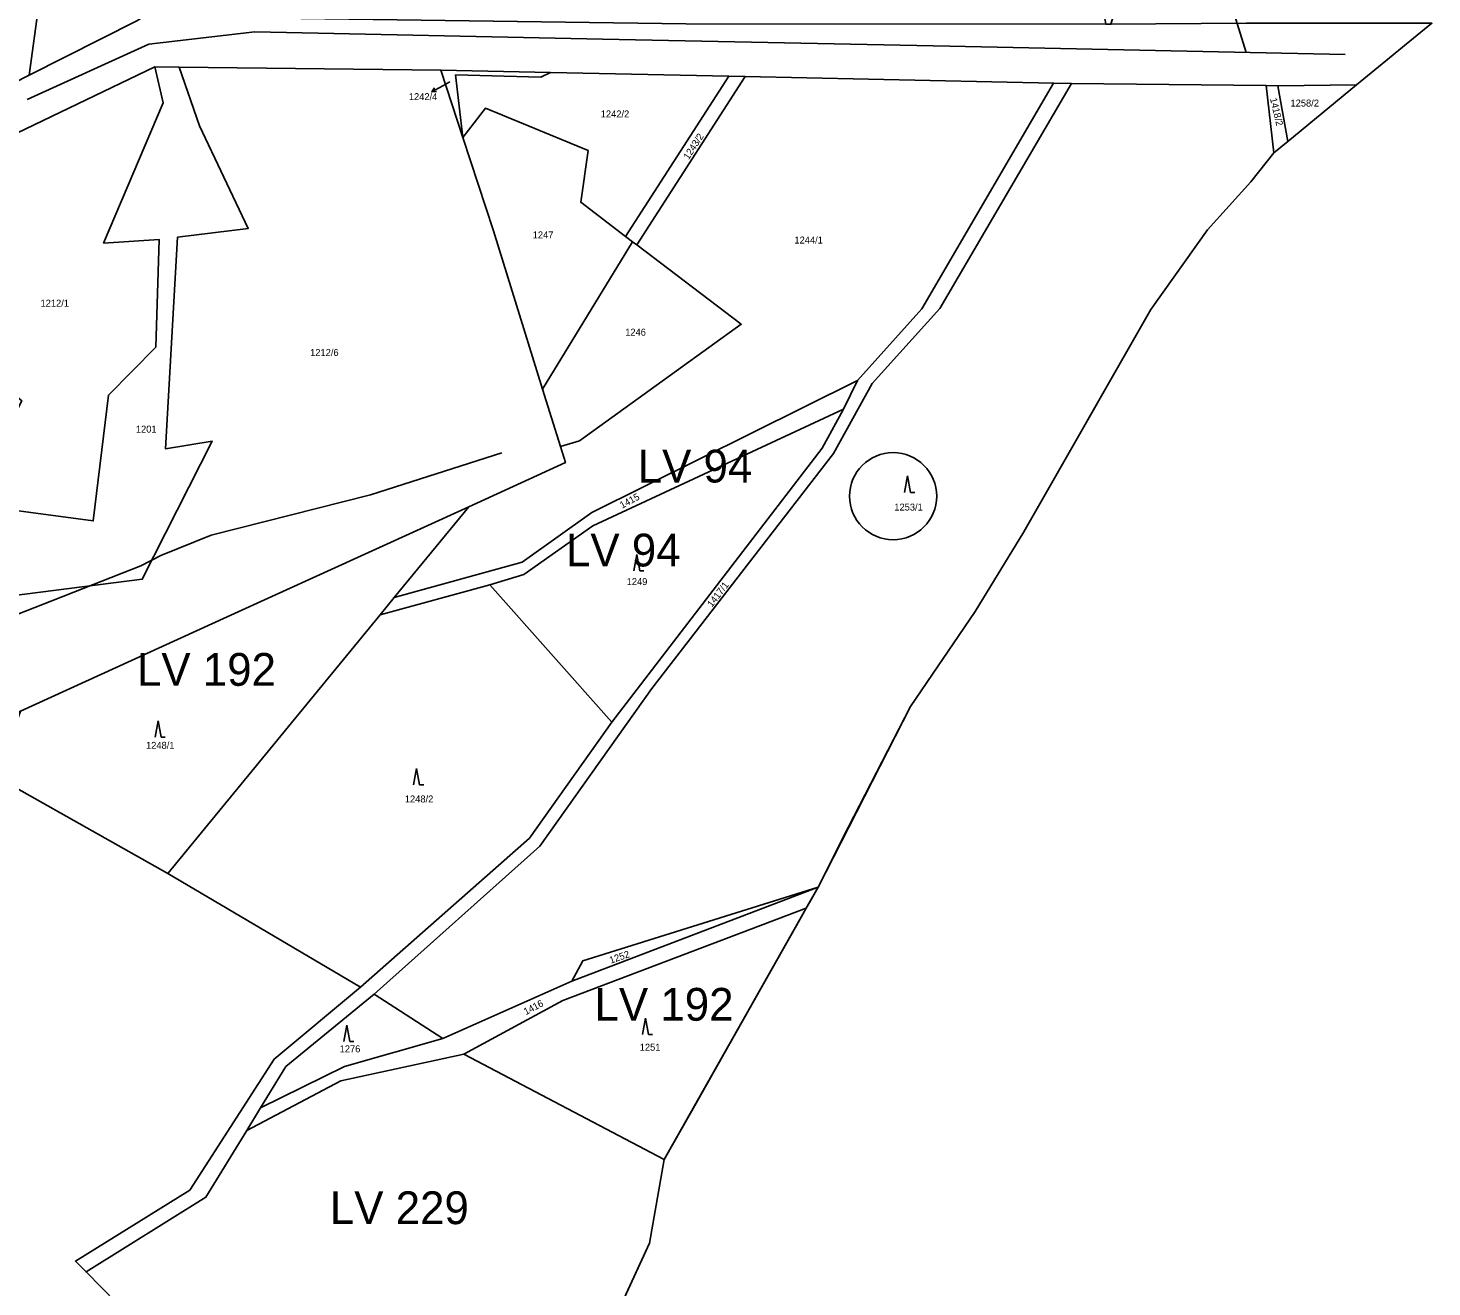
# Model space of a CAD drawing. Extents: x -588699 to -585793, y -1060280 to -1056731.
# Drawn here: x -587141.3 to -586798.8, y -1059816.3 to -1059509.1 of the extents above; entities that cross this region are included whole.
import ezdxf

# ---------------------------------------------------------------- set-up
doc = ezdxf.new("R2010")
doc.units = 0
for name, color, linetype in [('Druh pozemku', 7, 'Continuous'), ('Lesy', 7, 'Continuous'), ('Parcela nároku', 7, 'Continuous'), ('Parcelní číslo', 7, 'Continuous'), ('Silnice', 7, 'Continuous'), ('Vnitřní obvod', 7, 'Continuous'), ('Vnější obvod', 7, 'Continuous'), ('Vnější obvod_k šeření', 7, 'Continuous'), ('Vnější obvod_převzatý', 7, 'Continuous'), ('Změna katastrální hranice', 7, 'Continuous')]:
    doc.layers.add(name, color=color, linetype=linetype)

msp = doc.modelspace()

# ---------------------------------------------------------------- linework, layer by layer
at = {"layer": 'Druh pozemku'}
for p, q in [((-586926.71, -1059618.38), (-586927.45, -1059622.38)), ((-586926.71, -1059618.38), (-586925.98, -1059622.38)), ((-586925.98, -1059622.38), (-586924.98, -1059622.38)), ((-586992.76, -1059637.58), (-586993.49, -1059641.58)), ((-586992.76, -1059637.58), (-586992.03, -1059641.58)), ((-586992.03, -1059641.58), (-586991.03, -1059641.58)), ((-587109.57, -1059678.13), (-587110.31, -1059682.13)), ((-587109.57, -1059678.13), (-587108.84, -1059682.13)), ((-587108.84, -1059682.13), (-587107.84, -1059682.13)), ((-587046.49, -1059689.78), (-587047.22, -1059693.78)), ((-587046.49, -1059689.78), (-587045.76, -1059693.78)), ((-587045.76, -1059693.78), (-587044.76, -1059693.78)), ((-587063.55, -1059752.41), (-587064.29, -1059756.41)), ((-587063.55, -1059752.41), (-587062.82, -1059756.41)), ((-586990.66, -1059750.71), (-586991.4, -1059754.71)), ((-586990.66, -1059750.71), (-586989.93, -1059754.71)), ((-587062.82, -1059756.41), (-587061.82, -1059756.41)), ((-586989.93, -1059754.71), (-586988.93, -1059754.71))]:
    msp.add_line(p, q, dxfattribs=at)
at = {"layer": 'Lesy'}
msp.add_lwpolyline([(-587141.05, -1059520.54), (-587119.83, -1059365.24), (-587078.9, -1059331.95), (-586969.62, -1059361.59), (-586966.76, -1059361.84), (-586956.3, -1059359.21), (-586947.21, -1059358.99), (-586942.18, -1059361.29), (-586936.22, -1059370.55), (-586923.3, -1059391.32), (-586910.39, -1059412.1), (-586900.48, -1059424.78), (-586873.49, -1059457.5), (-586863.97, -1059469.8), (-586867.63, -1059482.1), (-586871.32, -1059488.5), (-586875.06, -1059501.23), (-586877.11, -1059508.12), (-586878.33, -1059508.13), (-586980.84, -1059508.07), (-587033.64, -1059507.3), (-587086.44, -1059506.54), (-587099.64, -1059497.72), (-587114.74, -1059507.28)], close=True, dxfattribs=at)
at = {"layer": 'Parcela nároku'}
for points in [[(-587144.52, -1059384.64), (-587133.01, -1059346.51), (-587118.08, -1059303.27), (-587048.58, -1059316.54), (-587020.31, -1059260.9), (-587008.46, -1059270.51), (-587003.28, -1059281.14), (-586985.82, -1059303.13), (-586963.83, -1059324.3), (-586960.97, -1059331.23), (-586967.8, -1059357.02), (-586969.62, -1059361.59), (-587078.9, -1059331.95), (-587119.83, -1059365.24), (-587141.05, -1059520.54), (-587157.06, -1059528.68), (-587170.06, -1059537.69), (-587133.46, -1059446.06), (-587144.92, -1059434.42), (-587164.2, -1059414.98)], [(-586890.56, -1059437.45), (-586910.39, -1059412.1), (-586936.22, -1059370.55), (-586966.76, -1059361.84), (-586969.62, -1059361.59), (-587078.9, -1059331.95), (-587119.83, -1059365.24), (-587141.05, -1059520.54), (-587114.74, -1059507.28), (-587099.64, -1059497.72), (-587086.44, -1059506.54), (-586980.84, -1059508.07), (-586878.33, -1059508.13), (-586878.5, -1059507.16), (-586879.3, -1059502.35), (-586889.86, -1059441.29)], [(-587152.88, -1059581.98), (-587153.88, -1059590.92), (-587142.82, -1059600.04), (-587155.89, -1059625.25), (-587125.4, -1059629.36), (-587121.68, -1059598.65), (-587110.15, -1059586.92), (-587109.34, -1059560.63), (-587122.86, -1059561.53), (-587108.33, -1059527.33), (-587110.39, -1059518.52), (-587150.41, -1059537.73), (-587184.41, -1059564.49), (-587181.88, -1059572.25), (-587173.88, -1059573.26)], [(-587110.15, -1059586.92), (-587121.68, -1059598.65), (-587125.4, -1059629.36), (-587155.89, -1059625.25), (-587142.82, -1059600.04), (-587153.88, -1059590.92), (-587152.88, -1059581.98), (-587173.88, -1059573.26), (-587181.88, -1059572.25), (-587156.82, -1059649.13), (-587113.45, -1059643.6), (-587096.36, -1059609.93), (-587107.78, -1059611.76), (-587104.87, -1059560.13), (-587087.56, -1059557.95), (-587099.48, -1059532.92), (-587104.46, -1059518.59), (-587110.39, -1059518.52), (-587108.33, -1059527.33), (-587122.86, -1059561.53), (-587109.34, -1059560.63)], [(-587104.87, -1059560.13), (-587087.56, -1059557.95), (-587099.48, -1059532.92), (-587104.46, -1059518.59), (-587040.59, -1059519.32), (-587035.21, -1059535.76), (-587027.75, -1059558.57), (-587015.76, -1059597.2), (-587011.41, -1059611.21), (-587010.19, -1059615.13), (-587033.76, -1059625.88), (-587092.75, -1059652.79), (-587143.14, -1059675.76), (-587147.48, -1059677.78), (-587154.14, -1059657.35), (-587156.82, -1059649.13), (-587113.45, -1059643.6), (-587096.36, -1059609.93), (-587107.78, -1059611.76)], [(-587040.59, -1059519.32), (-587013.85, -1059519.88), (-587016.17, -1059521.09), (-587036.99, -1059520.49), (-587035.21, -1059535.76)], [(-587016.17, -1059521.09), (-587013.85, -1059519.88), (-586970.34, -1059520.77), (-586995.52, -1059559.9), (-587006.45, -1059551.59), (-587004.67, -1059538.97), (-587029.73, -1059528.62), (-587035.21, -1059535.76), (-587036.99, -1059520.49)], [(-586942.36, -1059602.12), (-586947.53, -1059611.64), (-586998.9, -1059678.47), (-587018.95, -1059706.76), (-587060.16, -1059743.18), (-587081.25, -1059760.71), (-587101.83, -1059792.71), (-587129.74, -1059810), (-587127.15, -1059812.64), (-587097.9, -1059794.42), (-587087.95, -1059778.15), (-587084.56, -1059772.61), (-587078.4, -1059762.53), (-587056.87, -1059744.87), (-587016.41, -1059708.73), (-586989.15, -1059670.28), (-586944.8, -1059612.88), (-586935.38, -1059595.78), (-586918.84, -1059577.48), (-586886.77, -1059522.58), (-586891.09, -1059522.49), (-586923.21, -1059577.59), (-586938.9, -1059595.11)], [(-586941.19, -1059704.17), (-586926.03, -1059674.66), (-586910.21, -1059651.47), (-586898.36, -1059632.05), (-586893.45, -1059623.45), (-586867.35, -1059577.78), (-586853.53, -1059558.35), (-586843.02, -1059546.6), (-586837.4, -1059539.55), (-586839.27, -1059523.1), (-586886.77, -1059522.58), (-586918.84, -1059577.48), (-586935.38, -1059595.78), (-586944.8, -1059612.88), (-586989.15, -1059670.28), (-587016.41, -1059708.73), (-587056.87, -1059744.87), (-587040.07, -1059755.65), (-587008.61, -1059741.72), (-587005.93, -1059736.7), (-586948.53, -1059718.72)], [(-587006.77, -1059609.82), (-587011.41, -1059611.21), (-587010.19, -1059615.13), (-587033.76, -1059625.88), (-587051.95, -1059648.06), (-587020.71, -1059639.44), (-587003.73, -1059627.3), (-586938.9, -1059595.11), (-586923.21, -1059577.59), (-586891.09, -1059522.49), (-586966.31, -1059520.89), (-586992.8, -1059561.97), (-586967.32, -1059581.35)], [(-586970.34, -1059520.77), (-586995.52, -1059559.9), (-586993.82, -1059561.2), (-586992.8, -1059561.97), (-586966.31, -1059520.89)], [(-586839.27, -1059523.1), (-586836.39, -1059523.13), (-586833.99, -1059536.75), (-586837.4, -1059539.55)], [(-586836.39, -1059523.13), (-586817.19, -1059522.96), (-586833.99, -1059536.75)], [(-587035.21, -1059535.76), (-587029.73, -1059528.62), (-587004.67, -1059538.97), (-587006.45, -1059551.59), (-586995.52, -1059559.9), (-586993.82, -1059561.2), (-587015.76, -1059597.2), (-587027.75, -1059558.57)], [(-587015.76, -1059597.2), (-586993.82, -1059561.2), (-586992.8, -1059561.97), (-586967.32, -1059581.35), (-587006.77, -1059609.82), (-587011.41, -1059611.21)], [(-587051.95, -1059648.06), (-587020.71, -1059639.44), (-587003.73, -1059627.3), (-586938.9, -1059595.11), (-586942.36, -1059602.12), (-587003.52, -1059630.59), (-587020.34, -1059642.42), (-587028.65, -1059644.92), (-587055.43, -1059652.3)], [(-587028.65, -1059644.92), (-587020.34, -1059642.42), (-587003.52, -1059630.59), (-586942.36, -1059602.12), (-586947.53, -1059611.64), (-586998.9, -1059678.47)], [(-587092.75, -1059652.79), (-587143.14, -1059675.76), (-587147.34, -1059687.77), (-587144.15, -1059694.61), (-587107.2, -1059715.41), (-587055.43, -1059652.3), (-587051.95, -1059648.06), (-587033.76, -1059625.88)], [(-586998.9, -1059678.47), (-587028.65, -1059644.92), (-587055.43, -1059652.3), (-587107.2, -1059715.41), (-587060.16, -1059743.18), (-587018.95, -1059706.76)], [(-587087.95, -1059778.15), (-587084.56, -1059772.61), (-587064.1, -1059762.54), (-587040.07, -1059755.65), (-587008.61, -1059741.72), (-586948.53, -1059718.72), (-586950.69, -1059722.53), (-586951.46, -1059723.89), (-587010.84, -1059746.41), (-587034.94, -1059759.47), (-587064.95, -1059766.05)], [(-587008.61, -1059741.72), (-587005.93, -1059736.7), (-586948.53, -1059718.72)], [(-587034.94, -1059759.47), (-587010.84, -1059746.41), (-586951.46, -1059723.89), (-586953.1, -1059726.79), (-586961.57, -1059741.75), (-586979.69, -1059773.93), (-586986.11, -1059785.21)], [(-587056.87, -1059744.87), (-587040.07, -1059755.65), (-587064.1, -1059762.54), (-587084.56, -1059772.61), (-587078.4, -1059762.53)], [(-587005.04, -1059839.1), (-586989.72, -1059805.62), (-586986.11, -1059785.21), (-587034.94, -1059759.47), (-587064.95, -1059766.05), (-587087.95, -1059778.15), (-587097.9, -1059794.42), (-587127.15, -1059812.64), (-587078.67, -1059862.15), (-587079.78, -1059883.41), (-587069.15, -1059889.61), (-587058.18, -1059906.2), (-587040.05, -1059921.68), (-587025, -1059895.09)]]:
    msp.add_lwpolyline(points, close=True, dxfattribs=at)
for points in [[(-587150.41, -1059537.73), (-587110.39, -1059518.52), (-587104.46, -1059518.59), (-587040.59, -1059519.32), (-587013.85, -1059519.88), (-586970.34, -1059520.77), (-586966.31, -1059520.89), (-586891.09, -1059522.49), (-586886.77, -1059522.58), (-586839.27, -1059523.1), (-586836.39, -1059523.13), (-586817.19, -1059522.96), (-586798.8, -1059507.87), (-586840.64, -1059507.86), (-586844.13, -1059507.89), (-586877.11, -1059508.12), (-586878.33, -1059508.13), (-586980.84, -1059508.07), (-587086.44, -1059506.54), (-587099.64, -1059497.72), (-587114.74, -1059507.28), (-587141.05, -1059520.54), (-587157.06, -1059528.68)], [(-587144.15, -1059694.61), (-587107.2, -1059715.41), (-587060.16, -1059743.18), (-587081.25, -1059760.71), (-587101.83, -1059792.71), (-587129.74, -1059810), (-587127.15, -1059812.64), (-587078.67, -1059862.15)]]:
    msp.add_lwpolyline(points, dxfattribs=at)
at = {"layer": 'Parcelní číslo'}
for p, q in [((-587040.13, -1059523.14), (-587042.75, -1059524.6)), ((-587038.36, -1059522.16), (-587040.13, -1059523.14))]:
    msp.add_line(p, q, dxfattribs=at)
msp.add_lwpolyline([(-587041.64, -1059524.55), (-587042.75, -1059524.6), (-587042.12, -1059523.67)], dxfattribs=at)
at = {"layer": 'Silnice'}
for p, q in [((-587141.53, -1059526.46), (-587111.86, -1059513)), ((-587111.86, -1059513), (-587085.93, -1059510)), ((-587085.93, -1059510), (-587001.17, -1059511.75)), ((-587001.17, -1059511.75), (-586916.41, -1059513.5)), ((-586916.41, -1059513.5), (-586819.94, -1059515.49))]:
    msp.add_line(p, q, dxfattribs=at)
at = {"layer": 'Vnitřní obvod'}
msp.add_lwpolyline([(-586844.12, -1059514.99), (-586848.5, -1059500.78), (-586855.59, -1059481.48), (-586859.68, -1059471.81), (-586872.13, -1059455.98), (-586885.17, -1059443.76), (-586894.62, -1059434.91), (-586906.85, -1059418.68), (-586920.25, -1059394.05), (-586934.01, -1059370), (-586939.2, -1059365.92)], dxfattribs=at)
at = {"layer": 'Vnější obvod'}
for p, q in [((-586817.19, -1059522.96), (-586798.8, -1059507.87)), ((-586833.99, -1059536.75), (-586817.19, -1059522.96)), ((-586837.4, -1059539.55), (-586833.99, -1059536.75)), ((-586843.02, -1059546.6), (-586837.4, -1059539.55)), ((-586848.28, -1059552.48), (-586843.02, -1059546.6)), ((-586853.53, -1059558.35), (-586848.28, -1059552.48)), ((-586867.35, -1059577.78), (-586853.53, -1059558.35)), ((-586898.36, -1059632.05), (-586867.35, -1059577.78)), ((-586910.21, -1059651.47), (-586898.36, -1059632.05)), ((-586926.03, -1059674.66), (-586910.21, -1059651.47)), ((-586948.53, -1059718.72), (-586926.03, -1059674.66)), ((-586951.46, -1059723.89), (-586948.53, -1059718.72)), ((-586986.11, -1059785.21), (-586952.28, -1059725.34)), ((-586952.28, -1059725.34), (-586951.46, -1059723.89)), ((-586989.72, -1059805.62), (-586986.11, -1059785.21)), ((-586997.38, -1059822.36), (-586989.72, -1059805.62))]:
    msp.add_line(p, q, dxfattribs=at)
at = {"layer": 'Vnější obvod_k šeření'}
msp.add_lwpolyline([(-587545.78, -1059806.46), (-587503.79, -1059784.83), (-587475.53, -1059767.21), (-587420.62, -1059739.63), (-587331.51, -1059709.19), (-587275.57, -1059693.63), (-587242.96, -1059678.41), (-587207.73, -1059665.02), (-587184.16, -1059654.3), (-587149.27, -1059654.23), (-587113.78, -1059640.29), (-587108.9, -1059637.79), (-587096.59, -1059632.86), (-587057.74, -1059623), (-587025.71, -1059612.76)], dxfattribs=at)
at = {"layer": 'Vnější obvod_převzatý'}
msp.add_line((-586986.11, -1059785.21), (-587034.94, -1059759.47), dxfattribs=at)
msp.add_lwpolyline([(-586938.9, -1059595.11), (-587003.73, -1059627.3), (-587020.71, -1059639.44), (-587051.95, -1059648.06), (-587055.43, -1059652.3), (-587107.2, -1059715.41), (-587144.15, -1059694.61), (-587147.34, -1059687.77), (-587201.15, -1059671.19), (-587269.94, -1059658.83), (-587311.4, -1059651.83), (-587327.31, -1059666.35), (-587341, -1059675.47)], dxfattribs=at)
at = {"layer": 'Změna katastrální hranice'}
msp.add_circle((-586930.25, -1059623.31), 10.63, dxfattribs=at)

# ---------------------------------------------------------------- texts
at = {"layer": 'Parcela nároku'}
for s, height, p in [('1242/4', 0.1, (-587038.56, -1059522.16)), ('1258/2', 1.7, (-586833.31, -1059528.22)), ('1242/2', 1.7, (-587001.58, -1059530.88)), ('1247', 1.7, (-587018.18, -1059560.4)), ('1244/1', 1.7, (-586954.33, -1059561.65)), ('1212/1', 1.7, (-587138.26, -1059577.05)), ('1246', 1.7, (-586995.62, -1059584.14)), ('1212/6', 1.7, (-587072.48, -1059589.1)), ('1201', 1.7, (-587114.99, -1059607.8)), ('1253/1', 1.7, (-586929.96, -1059626.83)), ('1249', 1.7, (-586995.26, -1059645.02)), ('1248/1', 1.7, (-587112.52, -1059684.98)), ('1248/2', 1.7, (-587049.38, -1059698.07)), ('1276', 1.7, (-587065.28, -1059759.06)), ('1251', 1.7, (-586992.07, -1059758.66))]:
    msp.add_text(s, height=height, dxfattribs=at).set_placement(p)
for s, rotation, p in [('1418/2', 283.3859, (-586838.32, -1059526.31)), ('1243/2', 57.1711, (-586980.13, -1059541.31)), ('1415', 28.3772, (-586996.37, -1059626.4)), ('1417/1', 52.6147, (-586974.44, -1059650.55)), ('1252', 19.0496, (-586999.14, -1059737.43)), ('1416', 27.6301, (-587019.85, -1059750))]:
    msp.add_text(s, height=1.7, rotation=rotation, dxfattribs=at).set_placement(p)
at = {"layer": 'Parcelní číslo'}
msp.add_text('1242/4', height=1.7, dxfattribs=at).set_placement((-587048.4, -1059526.66))
at = {"layer": 'Vnější obvod_převzatý'}
for s, p in [('LV 94', (-586992.55, -1059619.98)), ('LV 94', (-587010.05, -1059640.47)), ('LV 192', (-587114.72, -1059669.6)), ('LV 192', (-587003.09, -1059751.34)), ('LV 229', (-587067.67, -1059800.99))]:
    msp.add_text(s, height=8, dxfattribs=at).set_placement(p)

doc.saveas('drawing.dxf')
